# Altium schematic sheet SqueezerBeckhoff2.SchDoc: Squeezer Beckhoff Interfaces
size B; Organization: LIGO Laboratory; Address1: California Institute of Technology; Address2: Massachusetts Institute of Technology; SheetNumber: 39; SheetTotal: 39; DrawnBy: R.  Abbott; Engineer: R.  Abbott; PageSetup: Record=PageOptions¦CenterHorizontal=True¦CenterVertical=True¦PrintScale=1.09¦XCorrection=1.00¦YCorrection=1.00¦PrintKind=0¦BorderSize=5000000¦LeftOffset=0¦BottomOffset=0¦Orientation=2¦PaperLength=1000¦PaperWidth=1000¦Scale=100¦PaperSource=7¦PrintQuality=-4¦MediaType=1¦DitherType=10¦PaperKind=11x17¦PrintScaleMode=1
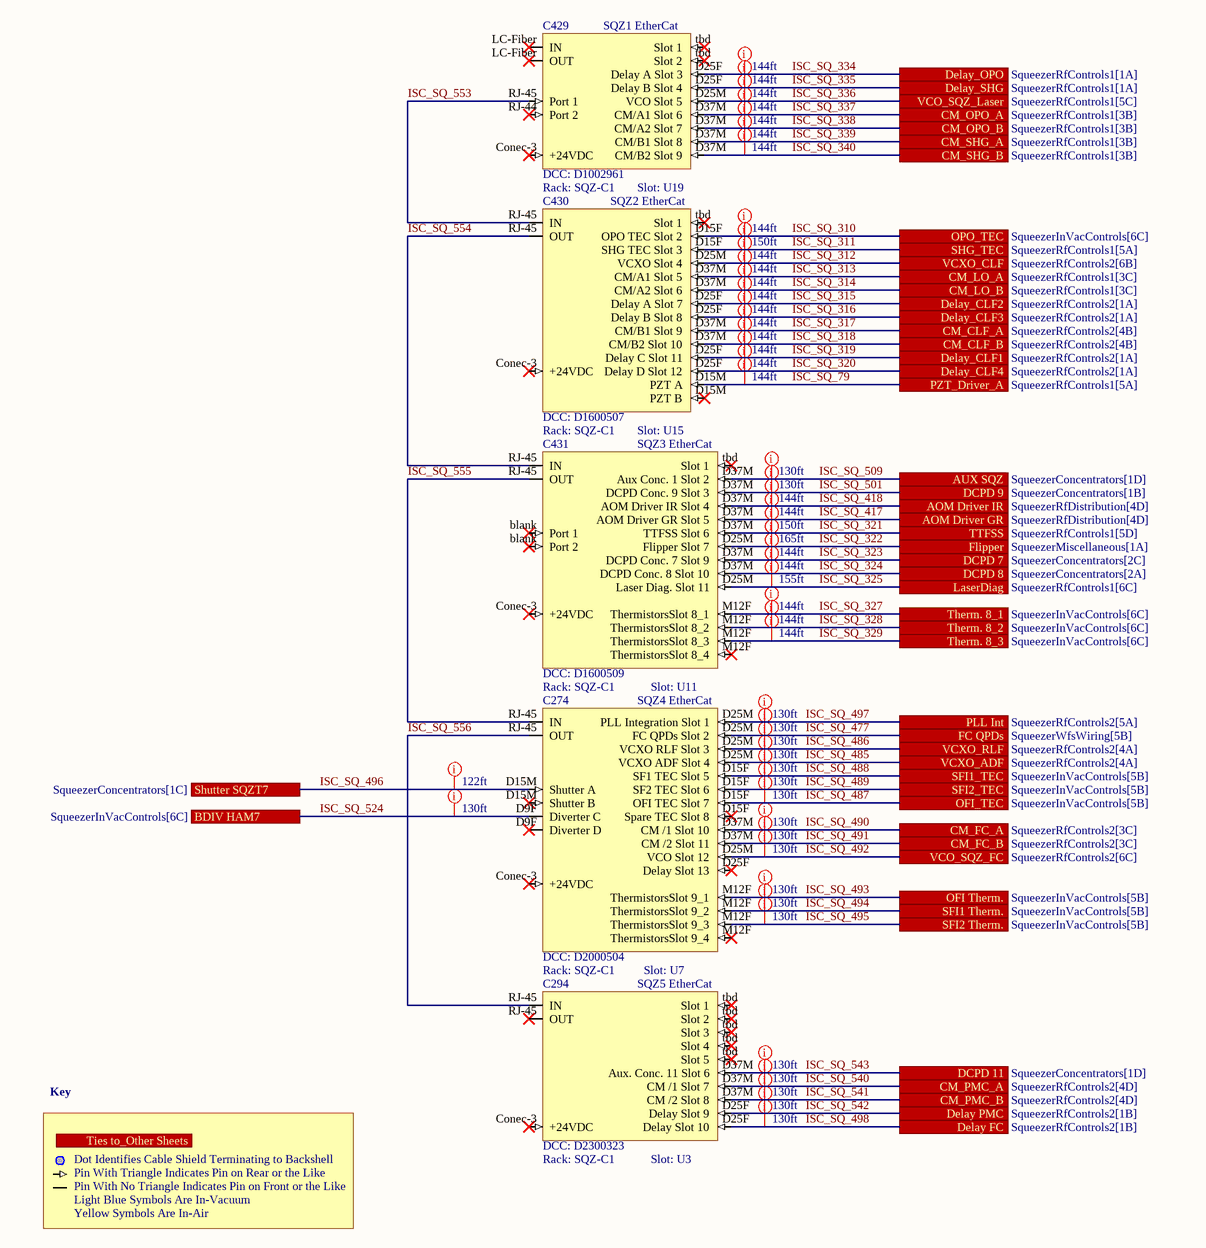
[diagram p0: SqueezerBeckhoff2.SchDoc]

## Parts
C274  SQZ4 EtherCat  DCC: D2000504  Rack: SQZ-C1  Slot: U7
C294  SQZ5 EtherCat  DCC: D2300323  Rack: SQZ-C1  Slot: U3
C429  SQZ1 EtherCat  DCC: D1002961  Rack: SQZ-C1  Slot: U19
C430  SQZ2 EtherCat  DCC: D1600507  Rack: SQZ-C1  Slot: U15
C431  SQZ3 EtherCat  DCC: D1600509  Rack: SQZ-C1  Slot: U11

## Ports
AOM Driver GR (see SqueezerRfDistribution[4D]), AOM Driver IR (see SqueezerRfDistribution[4D]), AUX SQZ (see SqueezerConcentrators[1D]), BDIV HAM7 (see SqueezerInVacControls[6C]), CM_CLF_A (see SqueezerRfControls2[4B]), CM_CLF_B (see SqueezerRfControls2[4B]), CM_FC_A (see SqueezerRfControls2[3C]), CM_FC_B (see SqueezerRfControls2[3C]), CM_LO_A (see SqueezerRfControls1[3C]), CM_LO_B (see SqueezerRfControls1[3C]), CM_OPO_A (see SqueezerRfControls1[3B]), CM_OPO_B (see SqueezerRfControls1[3B]), CM_PMC_A (see SqueezerRfControls2[4D]), CM_PMC_B (see SqueezerRfControls2[4D]), CM_SHG_A (see SqueezerRfControls1[3B]), CM_SHG_B (see SqueezerRfControls1[3B]), DCPD 7 (see SqueezerConcentrators[2C]), DCPD 8 (see SqueezerConcentrators[2A]), DCPD 9 (see SqueezerConcentrators[1B]), DCPD 11 (see SqueezerConcentrators[1D]), Delay FC (see SqueezerRfControls2[1B]), Delay PMC (see SqueezerRfControls2[1B]), Delay_CLF1 (see SqueezerRfControls2[1A]), Delay_CLF2 (see SqueezerRfControls2[1A]), Delay_CLF3 (see SqueezerRfControls2[1A]), Delay_CLF4 (see SqueezerRfControls2[1A]), Delay_OPO (see SqueezerRfControls1[1A]), Delay_SHG (see SqueezerRfControls1[1A]), FC QPDs (see SqueezerWfsWiring[5B]), Flipper (see SqueezerMiscellaneous[1A]), LaserDiag (see SqueezerRfControls1[6C]), OFI Therm. (see SqueezerInVacControls[5B]), OFI_TEC (see SqueezerInVacControls[5B]), OPO_TEC (see SqueezerInVacControls[6C]), PLL Int (see SqueezerRfControls2[5A]), PZT_Driver_A (see SqueezerRfControls1[5A]), SFI1 Therm. (see SqueezerInVacControls[5B]), SFI1_TEC (see SqueezerInVacControls[5B]), SFI2 Therm. (see SqueezerInVacControls[5B]), SFI2_TEC (see SqueezerInVacControls[5B]), SHG_TEC (see SqueezerRfControls1[5A]), Shutter SQZT7 (see SqueezerConcentrators[1C]), Therm. 8_1 (see SqueezerInVacControls[6C]), Therm. 8_2 (see SqueezerInVacControls[6C]), Therm. 8_3 (see SqueezerInVacControls[6C]), Ties to_Other Sheets, TTFSS (see SqueezerRfControls1[5D]), VCO_SQZ_FC (see SqueezerRfControls2[6C]), VCO_SQZ_Laser (see SqueezerRfControls1[5C]), VCXO_ADF (see SqueezerRfControls2[4A]), VCXO_CLF (see SqueezerRfControls2[6B]), VCXO_RLF (see SqueezerRfControls2[4A])

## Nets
ISC_SQ_79: C430.D15M(PZT_A) ; port PZT_Driver_A
ISC_SQ_310: C430.D15F(OPO_TEC_Slot_2) ; port OPO_TEC
ISC_SQ_311: C430.D15F(SHG_TEC_Slot_3) ; port SHG_TEC
ISC_SQ_312: C430.D25M(VCXO_Slot_4) ; port VCXO_CLF
ISC_SQ_313: C430.D37M(CM/A1_Slot_5) ; port CM_LO_A
ISC_SQ_314: C430.D37M(CM/A2_Slot_6) ; port CM_LO_B
ISC_SQ_315: C430.D25F(Delay_A_Slot_7) ; port Delay_CLF2
ISC_SQ_316: C430.D25F(Delay_B_Slot_8) ; port Delay_CLF3
ISC_SQ_317: C430.D37M(CM/B1_Slot_9) ; port CM_CLF_A
ISC_SQ_318: C430.D37M(CM/B2_Slot_10) ; port CM_CLF_B
ISC_SQ_319: C430.D25F(Delay_C_Slot_11) ; port Delay_CLF1
ISC_SQ_320: C430.D25F(Delay_D_Slot_12) ; port Delay_CLF4
ISC_SQ_321: C431.D37M(TTFSS_Slot_6) ; port TTFSS
ISC_SQ_322: C431.D25M(Flipper_Slot_7) ; port Flipper
ISC_SQ_323: C431.D37M(DCPD_Conc._7_Slot_9) ; port DCPD 7
ISC_SQ_324: C431.D37M(DCPD_Conc._8_Slot_10) ; port DCPD 8
ISC_SQ_325: C431.D25M(Laser_Diag._Slot_11) ; port LaserDiag
ISC_SQ_327: C431.M12F(ThermistorsSlot_8_1) ; port Therm. 8_1
ISC_SQ_328: C431.M12F(ThermistorsSlot_8_2) ; port Therm. 8_2
ISC_SQ_329: C431.M12F(ThermistorsSlot_8_3) ; port Therm. 8_3
ISC_SQ_334: C429.D25F(Delay_A_Slot_3) ; port Delay_OPO
ISC_SQ_335: C429.D25F(Delay_B_Slot_4) ; port Delay_SHG
ISC_SQ_336: C429.D25M(VCO_Slot_5) ; port VCO_SQZ_Laser
ISC_SQ_337: C429.D37M(CM/A1_Slot_6) ; port CM_OPO_A
ISC_SQ_338: C429.D37M(CM/A2_Slot_7) ; port CM_OPO_B
ISC_SQ_339: C429.D37M(CM/B1_Slot_8) ; port CM_SHG_A
ISC_SQ_340: C429.D37M(CM/B2_Slot_9) ; port CM_SHG_B
ISC_SQ_417: C431.D37M(AOM_Driver_GR_Slot_5) ; port AOM Driver GR
ISC_SQ_418: C431.D37M(AOM_Driver_IR_Slot_4) ; port AOM Driver IR
ISC_SQ_477: C274.D25M(FC_QPDs_Slot_2) ; port FC QPDs
ISC_SQ_485: C274.D25M(VCXO_ADF_Slot_4) ; port VCXO_ADF
ISC_SQ_486: C274.D25M(VCXO_RLF_Slot_3) ; port VCXO_RLF
ISC_SQ_487: C274.D15F(OFI_TEC_Slot_7) ; port OFI_TEC
ISC_SQ_488: C274.D15F(SF1_TEC_Slot_5) ; port SFI1_TEC
ISC_SQ_489: C274.D15F(Spare_TEC_Slot_8) ; port SFI2_TEC
ISC_SQ_490: C274.D37M(CM_/1_Slot_10) ; port CM_FC_A
ISC_SQ_491: C274.D37M(CM_/2_Slot_11) ; port CM_FC_B
ISC_SQ_492: C274.D25M(VCO_Slot_12) ; port VCO_SQZ_FC
ISC_SQ_493: C274.M12F(ThermistorsSlot_9_1) ; port OFI Therm.
ISC_SQ_494: C274.M12F(ThermistorsSlot_9_2) ; port SFI1 Therm.
ISC_SQ_495: C274.M12F(ThermistorsSlot_9_3) ; port SFI2 Therm.
ISC_SQ_496: C274.D15M(Shutter_A) ; port Shutter SQZT7
ISC_SQ_497: C274.D25M(PLL_Integration_Slot_1) ; port PLL Int
ISC_SQ_498: C294.D25F(Delay_Slot_10) ; port Delay FC
ISC_SQ_501: C431.D37M(DCPD_Conc._9_Slot_3) ; port DCPD 9
ISC_SQ_509: C431.D37M(Aux_Conc._1_Slot_2) ; port AUX SQZ
ISC_SQ_524: C274.D9F(Diverter_C) ; port BDIV HAM7
ISC_SQ_540: C294.D37M(CM_/1_Slot_7) ; port CM_PMC_A
ISC_SQ_541: C294.D37M(CM_/2_Slot_8) ; port CM_PMC_B
ISC_SQ_542: C294.D25F(Delay_Slot_9) ; port Delay PMC
ISC_SQ_543: C294.D37M(Aux._Conc._11_Slot_6) ; port DCPD 11
ISC_SQ_553: C429.RJ-45(Port_1) C430.RJ-45(IN)
ISC_SQ_554: C430.RJ-45(OUT) C431.RJ-45(IN)
ISC_SQ_555: C274.RJ-45(IN) C431.RJ-45(OUT)
ISC_SQ_556: C274.RJ-45(OUT) C294.RJ-45(IN)

Not connected (* = marked no-connect by the designer): C274 Conec-3(+24VDC)* D25F(Delay_Slot_13)*; C294 Conec-3(+24VDC)* tbd(Slot_1)*; C429 Conec-3(+24VDC)* LC-Fiber(IN)* RJ-44(Port_2)* tbd(Slot_1)*; C430 Conec-3(+24VDC)* tbd(Slot_1)*; C431 blank(Port_1)* Conec-3(+24VDC)* tbd(Slot_1)*

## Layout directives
Length: 144ft: ISC_SQ_79, ISC_SQ_310, ISC_SQ_312, ISC_SQ_313, ISC_SQ_314, ISC_SQ_315, ISC_SQ_316, ISC_SQ_317, ISC_SQ_318, ISC_SQ_319, ISC_SQ_320, ISC_SQ_323, ISC_SQ_324, ISC_SQ_327, ISC_SQ_328, ISC_SQ_329, ISC_SQ_334, ISC_SQ_335, ISC_SQ_336, ISC_SQ_337, ISC_SQ_338, ISC_SQ_339, ISC_SQ_340, ISC_SQ_417, ISC_SQ_418
Length: 150ft: ISC_SQ_311, ISC_SQ_321
Length: 155ft: ISC_SQ_325
Length: 165ft: ISC_SQ_322
Length: 130ft: ISC_SQ_477, ISC_SQ_485, ISC_SQ_486, ISC_SQ_487, ISC_SQ_488, ISC_SQ_489, ISC_SQ_490, ISC_SQ_491, ISC_SQ_492, ISC_SQ_493, ISC_SQ_494, ISC_SQ_495, ISC_SQ_497, ISC_SQ_498, ISC_SQ_501, ISC_SQ_509, ISC_SQ_524, ISC_SQ_540, ISC_SQ_541, ISC_SQ_542, ISC_SQ_543
Length: 122ft: ISC_SQ_496

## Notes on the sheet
- Key
- Dot Identifies Cable Shield Terminating to Backshell
- Pin With Triangle Indicates Pin on Rear or the Like
- Pin With No Triangle Indicates Pin on Front or the Like
- Light Blue Symbols Are In-Vacuum
- Yellow Symbols Are In-Air

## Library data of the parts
C274 = SQZ4 EtherCat: Serial: Sxxxxxxx; System: ISC
C294 = SQZ5 EtherCat: Serial: Sxxxxxxx; System: ISC
C429 = SQZ1 EtherCat: Serial: Sxxxxxxx; System: ISC
C430 = SQZ2 EtherCat: Serial: Sxxxxxxx; System: ISC
C431 = SQZ3 EtherCat: Serial: Sxxxxxxx; System: ISC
